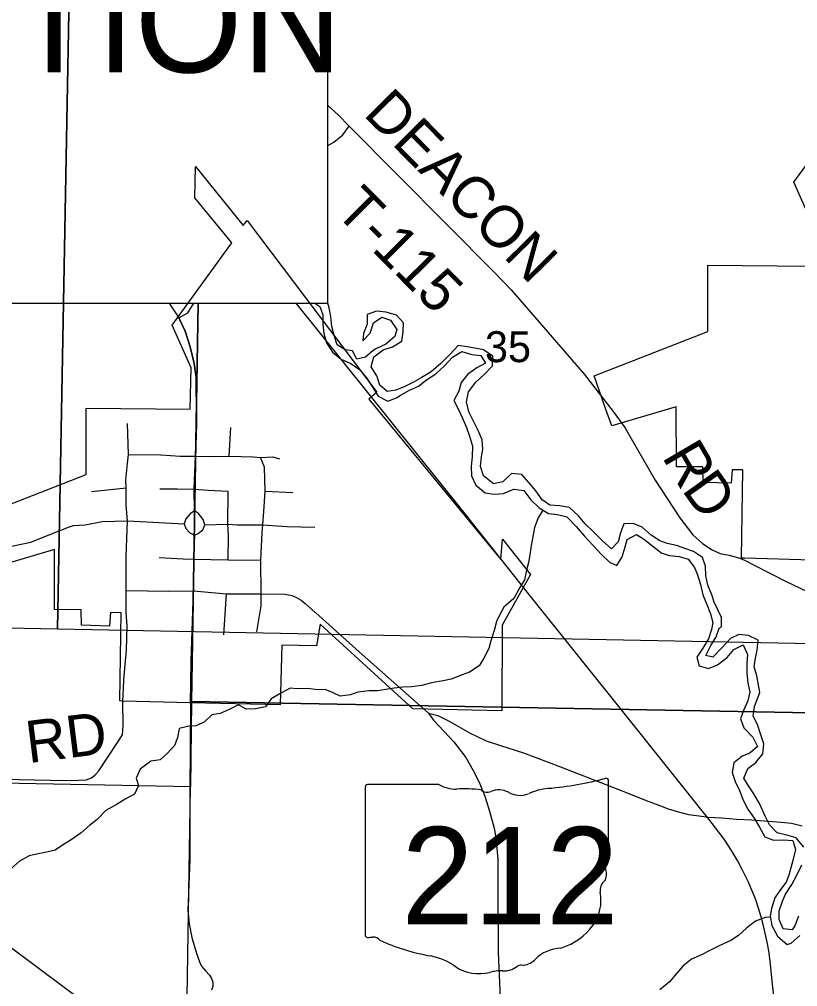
# Model space of a CAD drawing. Extents: x -19.9 to 41.9, y 0 to 32.3.
# Drawn here: x 3.98 to 5.034, y 18.417 to 19.727 of the extents above; entities that cross this region are included whole.
import ezdxf

# ---------------------------------------------------------------- set-up
doc = ezdxf.new("R2010")
doc.units = 0
for name, color, linetype in [('GM_X_City_Street', 7, 'Continuous'), ('GM_X_Corporation', 7, 'Continuous'), ('GM_X_County_Road', 7, 'Continuous'), ('GM_X_Major_River', 7, 'Continuous'), ('GM_X_Minor_River', 7, 'Continuous'), ('GM_X_Rail_Line', 7, 'Continuous'), ('GM_X_Section', 7, 'Continuous'), ('GM_X_Section_Text', 7, 'Continuous'), ('GM_X_State_Location', 7, 'Continuous'), ('GM_X_State_Route', 7, 'Continuous'), ('GM_X_State_Shield', 7, 'Continuous'), ('GM_X_Township_Road', 7, 'Continuous'), ('GM_X_Township_Road_Text', 7, 'Continuous'), ('SH_Text', 7, 'Continuous')]:
    doc.layers.add(name, color=color, linetype=linetype)

msp = doc.modelspace()

# ---------------------------------------------------------------- linework, layer by layer
at = {"layer": 'GM_X_City_Street'}
for p, q in [((4.2645, 19.1352), (4.2667, 19.1741)), ((4.0779, 19.0874), (4.1247, 19.0924)), ((4.3131, 19.0879), (4.3503, 19.086)), ((4.2569, 18.8935), (4.2605, 18.949))]:
    msp.add_line(p, q, dxfattribs=at)
for points in [[(4.1266, 19.1252), (4.1278, 19.1374), (4.1264, 19.1796)], [(4.1278, 19.1374), (4.1719, 19.1371), (4.1978, 19.1354), (4.2187, 19.1353), (4.2378, 19.1349), (4.2645, 19.1352), (4.297, 19.1343), (4.3067, 19.1335), (4.3234, 19.1343), (4.3325, 19.1318)], [(4.3076, 18.9381), (4.3074, 18.9487), (4.3071, 18.9945), (4.3089, 19.0318), (4.31, 19.0421), (4.3114, 19.0604), (4.3131, 19.0879), (4.3123, 19.1202), (4.3067, 19.1335)], [(4.1216, 18.8328), (4.1253, 18.8726), (4.126, 18.9055), (4.1248, 18.9236), (4.1246, 18.9533), (4.1246, 18.9996), (4.1265, 19.0477), (4.125, 19.0687), (4.1247, 19.0924), (4.1244, 19.1029), (4.1266, 19.1252)], [(4.1704, 19.091), (4.1937, 19.0908), (4.2167, 19.0905), (4.2358, 19.089), (4.2631, 19.0879)], [(4.263, 18.995), (4.2633, 19.028), (4.2625, 19.0432), (4.2631, 19.0879)], [(4.2312, 19.0422), (4.2625, 19.0432), (4.2753, 19.0421), (4.31, 19.0421), (4.3425, 19.0401), (4.3803, 19.0393)], [(4.1696, 18.998), (4.202, 18.9961), (4.2159, 18.9956), (4.263, 18.995), (4.3071, 18.9945)], [(4.1246, 18.9533), (4.1827, 18.9524), (4.2161, 18.9529)], [(4.212, 18.8005), (4.2127, 18.858), (4.2161, 18.9529)], [(4.3017, 18.8974), (4.3077, 18.9328), (4.3076, 18.9381)], [(4.1205, 18.8031), (4.1215, 18.8313), (4.1216, 18.8328)]]:
    msp.add_lwpolyline(points, dxfattribs=at)
at = {"layer": 'GM_X_Corporation'}
for points in [[(3.0491, 19.9448), (4.0503, 19.9079), (4.0319, 18.9009), (3.0393, 18.921)], [(4.0503, 19.9079), (5.0703, 19.9026), (5.0551, 18.9965), (5.0537, 18.8813), (4.0319, 18.9009)]]:
    msp.add_lwpolyline(points, close=True, dxfattribs=at)
for points in [[(5.0546, 19.4485), (5.029, 19.5062), (5.1101, 19.6175)], [(3.9167, 19.0506), (4.0707, 19.1103), (4.0707, 19.2003), (4.2114, 19.199), (4.2127, 19.255), (4.187, 19.3128), (4.2681, 19.424), (4.218, 19.485), (4.2189, 19.5276), (4.2834, 19.4475), (4.2887, 19.4544), (4.4644, 19.222), (4.4534, 19.2124), (4.6323, 18.9952), (4.6346, 19.0229), (4.6725, 18.9752), (4.6338, 18.9063), (4.6336, 18.7905), (4.5128, 18.7931), (4.3873, 18.9078), (4.3827, 18.8785), (4.3356, 18.8794), (4.3334, 18.7986), (4.2118, 18.8011), (4.1203, 18.8037), (4.1163, 18.8038), (4.1182, 18.9233), (4.1034, 18.9234), (4.1023, 18.9053), (4.0641, 18.9063), (4.0638, 18.9273), (4.0279, 18.9275), (4.0279, 19.0087), (3.9405, 18.9831)], [(5.0537, 18.9946), (4.9623, 18.9972), (4.9583, 18.9973), (4.9601, 19.1168), (4.9453, 19.1169), (4.9443, 19.0988), (4.9061, 19.0998), (4.9058, 19.1207), (4.8699, 19.1209), (4.8698, 19.2022), (4.7824, 19.1765), (4.7741, 19.1997), (4.7587, 19.2441), (4.9127, 19.3038), (4.9126, 19.3937), (5.0534, 19.3925)]]:
    msp.add_lwpolyline(points, dxfattribs=at)
at = {"layer": 'GM_X_County_Road'}
for p, q in [((4.2167, 19.0905), (4.2187, 19.1353)), ((4.2172, 19.0612), (4.2167, 19.0905))]:
    msp.add_line(p, q, dxfattribs=at)
for points in [[(4.3977, 19.5558), (4.406, 19.5602), (4.4181, 19.5704), (4.427, 19.5818), (4.412, 19.5975), (4.3977, 19.6099)], [(4.1959, 19.3224), (4.2082, 19.3295), (4.2162, 19.3423)], [(4.22, 19.1884), (4.2198, 19.2417), (4.217, 19.2605), (4.2115, 19.2831), (4.2049, 19.3046), (4.1959, 19.3224)], [(4.2187, 19.1353), (4.22, 19.1788), (4.22, 19.1884)], [(4.2312, 19.0422), (4.229, 19.0495), (4.2227, 19.0574), (4.2172, 19.0612)], [(3.9304, 19.005), (3.9323, 19.0057), (3.9955, 19.0186), (4.0212, 19.029), (4.0489, 19.0402), (4.0535, 19.0412), (4.061, 19.042), (4.0691, 19.0423), (4.0922, 19.0468), (4.1265, 19.0477), (4.2034, 19.0436)], [(4.2034, 19.0436), (4.2058, 19.0373), (4.2111, 19.0316), (4.2173, 19.0282)], [(4.2173, 19.0282), (4.2225, 19.0307), (4.2286, 19.0355), (4.2312, 19.0422)]]:
    msp.add_lwpolyline(points, dxfattribs=at)
at = {"layer": 'GM_X_Major_River'}
for points in [[(4.3805, 19.3423), (4.3871, 19.338), (4.3911, 19.3267), (4.3913, 19.3141), (4.3926, 19.3013), (4.3959, 19.2888), (4.4041, 19.276), (4.416, 19.2664), (4.429, 19.2605), (4.441, 19.2524), (4.4503, 19.2411), (4.4588, 19.2284), (4.4659, 19.2163), (4.4793, 19.2097), (4.4918, 19.2145)], [(4.4595, 19.2781), (4.4487, 19.2692), (4.4373, 19.2667), (4.4314, 19.278), (4.4215, 19.2794), (4.4104, 19.286), (4.4064, 19.2985), (4.4035, 19.3109), (4.4018, 19.3242), (4.3997, 19.3359), (4.3977, 19.3423)], [(4.931, 18.9041), (4.9308, 18.9166), (4.9264, 18.9264), (4.9213, 18.9377), (4.9177, 18.9475), (4.9126, 18.9604), (4.9097, 18.9732), (4.9095, 18.9861), (4.9055, 18.9982), (4.8932, 19.006), (4.8829, 19.01), (4.8699, 19.0143), (4.8573, 19.0171), (4.8477, 19.0208), (4.8358, 19.0282), (4.8235, 19.039), (4.8116, 19.0441), (4.7987, 19.0435), (4.7943, 19.0313), (4.7911, 19.0194), (4.7821, 19.0098), (4.7694, 19.021), (4.7578, 19.0329), (4.7462, 19.0438), (4.7373, 19.0546), (4.7253, 19.0658), (4.7116, 19.0678), (4.6987, 19.0688), (4.6883, 19.0762), (4.6794, 19.0882), (4.67, 19.0994), (4.6604, 19.1103), (4.6467, 19.1119), (4.6351, 19.1004), (4.6222, 19.0979), (4.6087, 19.1087), (4.6047, 19.1211), (4.606, 19.1348), (4.6077, 19.1443), (4.6071, 19.1572), (4.6016, 19.17), (4.5953, 19.1824), (4.589, 19.1952), (4.5858, 19.2088), (4.5882, 19.2225), (4.5982, 19.2356), (4.6095, 19.246), (4.6211, 19.2576), (4.6212, 19.2705), (4.6089, 19.279), (4.5994, 19.2812), (4.5864, 19.2832), (4.5746, 19.2849), (4.5634, 19.2733), (4.5507, 19.2606), (4.5379, 19.2494), (4.5244, 19.2412), (4.5146, 19.2357), (4.5022, 19.2295), (4.4901, 19.2247), (4.4783, 19.223), (4.4683, 19.2312), (4.4643, 19.244), (4.4565, 19.256), (4.4601, 19.2697), (4.4728, 19.2791), (4.4853, 19.2831), (4.4981, 19.2909), (4.4998, 19.3034), (4.5004, 19.3156), (4.4907, 19.326), (4.4769, 19.3304), (4.464, 19.3317), (4.4511, 19.3269), (4.451, 19.314), (4.4462, 19.3014), (4.4453, 19.2915), (4.4553, 19.3019), (4.4597, 19.3157), (4.471, 19.3234), (4.4828, 19.3195), (4.4914, 19.3067), (4.4885, 19.2972), (4.4765, 19.2867), (4.4629, 19.2804), (4.4595, 19.2781)], [(4.4918, 19.2145), (4.4951, 19.2168), (4.5087, 19.2246), (4.5208, 19.2298), (4.5317, 19.2387), (4.5441, 19.2465), (4.5557, 19.2577), (4.5669, 19.2692), (4.5793, 19.277), (4.5931, 19.2727), (4.6052, 19.2714), (4.6115, 19.2612), (4.5998, 19.255), (4.5874, 19.2464), (4.5785, 19.2349), (4.5753, 19.2231), (4.5686, 19.2108), (4.5745, 19.1995), (4.5796, 19.1875), (4.5859, 19.1739), (4.5896, 19.1622), (4.594, 19.1486), (4.5934, 19.135), (4.5918, 19.1213), (4.5924, 19.1084), (4.5983, 19.096), (4.611, 19.0855), (4.6232, 19.0838), (4.6357, 19.0848), (4.6497, 19.0907), (4.6634, 19.0887), (4.6727, 19.0759), (4.6839, 19.0655), (4.6966, 19.0577), (4.7088, 19.0564), (4.7217, 19.0532), (4.7341, 19.0401), (4.7454, 19.027), (4.7574, 19.0143), (4.7682, 19.0024), (4.7794, 18.9916), (4.7894, 18.9872), (4.7964, 18.999), (4.8007, 19.0124), (4.8032, 19.0223), (4.8157, 19.029), (4.8253, 19.0234), (4.838, 19.0134), (4.8503, 19.0041), (4.8606, 19.0009), (4.8739, 18.9992), (4.8858, 18.996), (4.8943, 18.9843), (4.8987, 18.9745), (4.9027, 18.9617), (4.9059, 18.9477), (4.9111, 18.9345), (4.9163, 18.9217), (4.9191, 18.91), (4.9174, 18.9005), (4.9134, 18.8879), (4.9056, 18.8752), (4.8978, 18.8633), (4.9007, 18.8512), (4.9133, 18.848), (4.9258, 18.8528), (4.9389, 18.8625), (4.9478, 18.8733), (4.9603, 18.8799), (4.9662, 18.8667), (4.9653, 18.8546), (4.9651, 18.8417), (4.9668, 18.8277), (4.9693, 18.8163), (4.9665, 18.8041), (4.9606, 18.7911), (4.9566, 18.7797), (4.9614, 18.7676), (4.9734, 18.7549), (4.9797, 18.7421), (4.9692, 18.7332), (4.959, 18.7292), (4.9477, 18.7199), (4.9453, 18.707), (4.9493, 18.6949), (4.9552, 18.6825), (4.9603, 18.6697), (4.9666, 18.6572), (4.9752, 18.6452), (4.9826, 18.6328), (4.9896, 18.6201), (5.0015, 18.6153), (5.0152, 18.6159), (5.0277, 18.615), (5.031, 18.6029), (5.0278, 18.588), (5.0249, 18.5777), (5.0224, 18.5682), (5.0184, 18.5583), (5.0098, 18.5471), (5.0032, 18.5372)], [(5.0427, 18.6061), (5.0322, 18.6185), (5.0196, 18.6221), (5.0063, 18.6253), (4.9958, 18.6361), (4.9903, 18.6478), (4.9828, 18.664), (4.9746, 18.6779), (4.9684, 18.6876), (4.9614, 18.6993), (4.9665, 18.7123), (4.9774, 18.7204), (4.987, 18.7324), (4.9883, 18.746), (4.9839, 18.7592), (4.9799, 18.7721), (4.974, 18.7834), (4.9757, 18.7963), (4.983, 18.8154), (4.9809, 18.8252), (4.9788, 18.8377), (4.9752, 18.8502), (4.9766, 18.8597), (4.9794, 18.8727), (4.9807, 18.886), (4.9677, 18.8926), (4.9547, 18.8939), (4.943, 18.8884), (4.9311, 18.8753), (4.9191, 18.8633), (4.9096, 18.8654), (4.9166, 18.8788), (4.9236, 18.8907), (4.928, 18.9022), (4.931, 18.9041)], [(5.0267, 18.4939), (5.0145, 18.4952), (5.009, 18.508), (5.0092, 18.5198), (5.0135, 18.5328), (5.0179, 18.5423), (5.0261, 18.5554), (5.0331, 18.568), (5.0397, 18.5822)], [(5.0032, 18.5372), (4.9985, 18.5227), (4.9971, 18.5124), (4.9992, 18.4999), (5.0067, 18.4856), (5.0198, 18.474)], [(5.0355, 18.5123), (5.0304, 18.4996), (5.0267, 18.4939)], [(5.0198, 18.474), (5.0255, 18.476), (5.0371, 18.4865)]]:
    msp.add_lwpolyline(points, dxfattribs=at)
at = {"layer": 'GM_X_Minor_River'}
for points in [[(4.6891, 19.0623), (4.6826, 19.0517), (4.6778, 19.0387), (4.6749, 19.0239), (4.6734, 19.0144), (4.6713, 19.0015), (4.6695, 18.9912), (4.6669, 18.981), (4.664, 18.968), (4.6565, 18.9554), (4.6497, 18.9425), (4.6362, 18.931), (4.6306, 18.9211), (4.6265, 18.9112), (4.6231, 18.8994), (4.6187, 18.8853), (4.6161, 18.875), (4.609, 18.8617), (4.603, 18.8514), (4.5898, 18.8429), (4.58, 18.8394), (4.5648, 18.8332), (4.5542, 18.8312), (4.5383, 18.8284), (4.5254, 18.8249), (4.5114, 18.8229), (4.4996, 18.8224), (4.4878, 18.8212), (4.4765, 18.8192), (4.4647, 18.8176), (4.4537, 18.8175), (4.4385, 18.8158), (4.4287, 18.8123), (4.4146, 18.8103), (4.4043, 18.8151), (4.3944, 18.8192), (4.3842, 18.8188), (4.3705, 18.8206), (4.3564, 18.8204), (4.3469, 18.8211), (4.3352, 18.8149), (4.3212, 18.8069), (4.3137, 18.7958), (4.3001, 18.793), (4.2875, 18.7925), (4.2769, 18.7985), (4.2644, 18.7923), (4.2519, 18.7869), (4.2409, 18.7849), (4.2303, 18.775), (4.219, 18.7703), (4.2095, 18.7695), (4.1966, 18.7667), (4.1944, 18.7538), (4.1904, 18.7435), (4.1809, 18.7332), (4.1708, 18.7243), (4.1583, 18.7223), (4.1439, 18.7116), (4.1383, 18.6994), (4.1414, 18.6892), (4.1362, 18.6777), (4.1234, 18.6708), (4.1128, 18.6639), (4.0973, 18.6554), (4.0856, 18.6435), (4.0754, 18.6355), (4.0637, 18.6251), (4.0501, 18.6159), (4.04, 18.6094), (4.0286, 18.6017), (4.015, 18.5989), (4.0055, 18.5969), (3.9934, 18.5942), (3.9805, 18.5868), (3.9688, 18.5765)], [(4.9973, 18.5112), (4.9903, 18.5108), (4.9771, 18.5057), (4.9654, 18.4965), (4.9541, 18.4865), (4.9435, 18.4796), (4.928, 18.4723), (4.9151, 18.4661), (4.9038, 18.4603), (4.8905, 18.4541), (4.8788, 18.4449), (4.8706, 18.4353), (4.8604, 18.4235), (4.8476, 18.4128)]]:
    msp.add_lwpolyline(points, dxfattribs=at)
at = {"layer": 'GM_X_Rail_Line'}
msp.add_lwpolyline([(5.0035, 18.3895), (5.0003, 18.4205), (4.9969, 18.4515), (4.9949, 18.4657), (4.9929, 18.4775), (4.9903, 18.4896), (4.9875, 18.5011), (4.9844, 18.5128), (4.9809, 18.5235), (4.9773, 18.5344), (4.9735, 18.5446), (4.9671, 18.5596), (4.9596, 18.5747), (4.9526, 18.5877), (4.9461, 18.5993), (4.9404, 18.6078), (4.9346, 18.6167), (4.9158, 18.6416), (4.8026, 18.783), (4.6702, 18.9484), (4.5819, 19.0594), (4.3549, 19.3423)], dxfattribs=at)
at = {"layer": 'GM_X_Section'}
for points in [[(4.3977, 19.8017), (5.0763, 19.7825), (5.0521, 18.7876), (4.2131, 18.8031), (4.2222, 19.3423)], [(4.2222, 19.3423), (4.2131, 18.8031), (4.2117, 18.6878), (3.19, 18.7074), (3.2015, 19.3423)]]:
    msp.add_lwpolyline(points, dxfattribs=at)
msp.add_lwpolyline([(4.2131, 18.8031), (5.0521, 18.7876), (5.0351, 17.7675), (4.1973, 17.7768), (4.2117, 18.6878)], close=True, dxfattribs=at)
at = {"layer": 'GM_X_State_Route'}
for p, q in [((4.183, 19.3423), (4.1852, 19.3389)), ((4.1852, 19.3389), (4.1959, 19.3224)), ((4.2187, 19.1353), (4.2167, 19.0905)), ((4.2167, 19.0905), (4.2172, 19.0612)), ((4.5187, 18.801), (4.5341, 18.7874))]:
    msp.add_line(p, q, dxfattribs=at)
for points in [[(4.1959, 19.3224), (4.2049, 19.3046), (4.2115, 19.2831), (4.217, 19.2605), (4.2198, 19.2417), (4.22, 19.1884)], [(4.22, 19.1884), (4.22, 19.1788), (4.2187, 19.1353)], [(4.2172, 19.0612), (4.2113, 19.0572), (4.2056, 19.0504), (4.2034, 19.0436)], [(4.2312, 19.0422), (4.229, 19.0495), (4.2227, 19.0574), (4.2172, 19.0612)], [(4.2034, 19.0436), (4.2058, 19.0373), (4.2111, 19.0316), (4.2173, 19.0282)], [(4.2173, 19.0282), (4.2225, 19.0307), (4.2286, 19.0355), (4.2312, 19.0422)], [(4.2173, 19.0282), (4.2159, 18.9956), (4.2161, 18.9529), (4.2605, 18.949), (4.3074, 18.9487), (4.34, 18.9482), (4.349, 18.9468), (4.3553, 18.944), (4.362, 18.9405), (4.3671, 18.9358), (4.3809, 18.9237)], [(4.3809, 18.9237), (4.3817, 18.923), (4.4401, 18.8703), (4.5187, 18.801)], [(4.5341, 18.7874), (4.5469, 18.7842), (4.5633, 18.7759), (4.5896, 18.7608), (4.6123, 18.75), (4.6318, 18.7437), (4.6627, 18.7335), (4.7132, 18.7145), (4.7904, 18.6845), (4.8146, 18.675), (4.8291, 18.6693), (4.8461, 18.6627), (4.8588, 18.6578), (4.8741, 18.6532), (4.8863, 18.6501), (4.9009, 18.6482), (4.9128, 18.6467), (4.9312, 18.6457), (4.9519, 18.644), (4.9723, 18.6429), (5.012, 18.6397), (5.0259, 18.6383), (5.0402, 18.6346)], [(4.5341, 18.7874), (4.5411, 18.778), (4.5687, 18.7486), (4.5846, 18.7275), (4.5948, 18.7097), (4.6029, 18.694), (4.6103, 18.675), (4.6167, 18.6547), (4.6231, 18.6316), (4.6256, 18.6186), (4.628, 18.5902), (4.6283, 18.5578), (4.6286, 18.4634), (4.6311, 18.4021)]]:
    msp.add_lwpolyline(points, dxfattribs=at)
at = {"layer": 'GM_X_State_Shield'}
for p, q in [((4.4486, 18.6874), (4.4486, 18.4873)), ((4.5484, 18.6908), (4.4518, 18.6908)), ((4.7782, 18.5911), (4.7782, 18.6958)), ((4.7781, 18.5911), (4.7782, 18.5911))]:
    msp.add_line(p, q, dxfattribs=at)
for centre, major_axis, start_param, end_param in [((4.4524, 18.6878), (0.00382, 0), 1.712693, 3.28349), ((4.5713, 18.7141), (0.037, 0), 4.042523, 4.731795), ((4.6608, 18.9637), (0.3495, 0), 4.814394, 5.042369), ((4.7745, 18.6962), (0.00367, 0), 6.141152, 7.989035), ((4.5836, 18.5785), (0.133, 0), 1.404758, 1.657858), ((4.6138, 18.6888), (0.0107, 0), 3.836095, 5.185415), ((4.6295, 18.6657), (0.0222, 0), 0.950623, 2.079405), ((4.6582, 18.6974), (0.0267, 0), 4.081561, 5.145723), ((4.7054, 18.6297), (0.0703, 0), 1.699011, 2.107814), ((4.7773, 18.5834), (0.00568, 0), 1.883978, 3.671073), ((4.7743, 18.5907), (0.00393, 0), 5.05454, 6.418171), ((4.7412, 18.5702), (0.0341, 0), 5.934695, 6.695948), ((4.7913, 18.5473), (0.0248, 0), 2.387724, 3.262537), ((4.6804, 18.534), (0.0874, 0), 5.101752, 6.440018), ((4.4524, 18.4868), (0.00385, 0), 3.00124, 4.508301), ((4.453, 18.5073), (0.0294, 0), 4.665946, 4.897461), ((4.459, 18.4757), (0.0106, 0), 0.519207, 1.627899), ((4.5928, 18.6555), (0.2524, 0), 4.195997, 4.488961), ((4.7172, 18.4311), (0.0479, 0), 1.647645, 2.488434), ((4.5176, 18.3974), (0.079, 0), 0.823519, 1.323587), ((4.6566, 18.4679), (0.0282, 0), 4.937069, 5.64225), ((4.603, 18.4747), (0.0501, 0), 4.026481, 4.996735), ((4.6319, 18.4055), (0.0412, 0), 1.495662, 1.94098), ((4.6356, 18.4597), (0.0267, 0), 4.691044, 5.507374), ((4.6598, 18.4404), (0.00752, 0), 1.147584, 2.315152)]:
    msp.add_ellipse(centre, major_axis=major_axis, ratio=0.8, start_param=start_param, end_param=end_param, dxfattribs=at)
at = {"layer": 'GM_X_Township_Road'}
for points in [[(4.427, 19.5818), (4.6241, 19.3834), (4.646, 19.3602), (4.7455, 19.2457), (4.7845, 19.1958), (4.7999, 19.1739), (4.8414, 19.1028), (4.8748, 19.0516), (4.8924, 19.0287), (4.9051, 19.017), (4.9183, 19.0086), (4.9292, 19.0035), (4.9415, 19.0011), (4.9558, 18.997), (4.962, 18.9944), (4.9751, 18.9875), (5.0179, 18.9661), (5.0469, 18.9521)], [(3.6957, 18.6659), (3.7593, 18.6719), (3.7672, 18.6734), (3.7699, 18.674), (3.7824, 18.6796), (3.8205, 18.6985), (3.8232, 18.6993), (3.8265, 18.7), (3.83, 18.7005), (3.8483, 18.7001), (4.044, 18.6962), (4.0604, 18.6965), (4.0708, 18.697), (4.0777, 18.6999), (4.0826, 18.7037), (4.0878, 18.7094), (4.1131, 18.7477), (4.1198, 18.7579), (4.1209, 18.7708), (4.1205, 18.8031)], [(4.212, 18.8005), (4.2108, 18.6817), (4.211, 18.5891), (4.2081, 18.5204), (4.2099, 18.5022), (4.2137, 18.4835), (4.2179, 18.4698), (4.2213, 18.4583), (4.2241, 18.4506), (4.2267, 18.4448), (4.2321, 18.4387), (4.2375, 18.4325), (4.2404, 18.428), (4.242, 18.4233), (4.2423, 18.4174), (4.2404, 18.4121)]]:
    msp.add_lwpolyline(points, dxfattribs=at)
at = {"layer": 'SH_Text'}
for points in [[(2.4893, 19.3423), (4.3977, 19.3423), (4.3977, 19.8611), (2.4893, 19.8611)], [(2.8043, 19.3392), (5.2749, 17.495), (2.4893, 19.3392)]]:
    msp.add_lwpolyline(points, close=True, dxfattribs=at)

# ---------------------------------------------------------------- texts
at = {"layer": 'GM_X_Section_Text'}
msp.add_text('35', height=0.04186, rotation=0, dxfattribs=at).set_placement((4.6107, 19.2625))
at = {"layer": 'GM_X_State_Location'}
for s in ['s', 'r']:
    msp.add_text(s, height=0.000189, dxfattribs=at).set_placement((4.6097, 18.574))
msp.add_text('212', height=0.000189, rotation=0, dxfattribs=at).set_placement((4.5428, 18.5602))
at = {"layer": 'GM_X_State_Shield'}
msp.add_text('212', height=0.13184, dxfattribs=at).set_placement((4.4976, 18.5014))
at = {"layer": 'GM_X_Township_Road_Text'}
for s, height, rotation, p in [('DEACON', 0.05682, 314.6496, (4.4446, 19.5973)), ('T-115', 0.05682, 314.8019, (4.4054, 19.4655)), ('R', 0.0568, 300.3205, (4.8497, 19.1346)), ('D', 0.0568, 305.6153, (4.8763, 19.0896)), ('RD', 0.05682, 7.1885, (3.9925, 18.7196))]:
    msp.add_text(s, height=height, rotation=rotation, dxfattribs=at).set_placement(p)
at = {"layer": 'SH_Text'}
msp.add_text('PROJECT LOCATION', height=0.14, dxfattribs=at).set_placement((2.5347, 19.6548))

doc.saveas('drawing.dxf')
